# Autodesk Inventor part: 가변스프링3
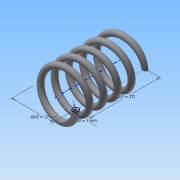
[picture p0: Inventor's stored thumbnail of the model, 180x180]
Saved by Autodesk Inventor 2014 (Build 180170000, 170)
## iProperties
Created: 2015-09
Part Number: 가변스프링3
Material: 강철, 탄소
Document SubType Name: Modeling
Designer: study
Density: 1 g/cm^3
Appearance: 반연마
Mass: 2.40066 g
Surface Area: 32.5308 cm^2
Volume: 2.40066 cm^3
Author: study
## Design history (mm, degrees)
sketch "스케치1"
  geometry: L1 (0, 0)-(11, 0); L2 (11, 0)-(11, 37); L3 (11, 37)-(0, 37); L4 (0, 37)-(0, 0); C1 r 1.5 at (11, 0)
  constraints: 8 end point, 2 parallel, 1 centre point, 1 coincident, 1 horizontal, 1 perpendicular
  dimensions: "d0" = 3 diameter of C1; "d2" = 22 diameter of L2 L4; "d3" = 37 distance of L1.end L2.end (derived)
feature "코일1" sketch "스케치1" pitch "d4" = 10; turns "d6" = 5; dims "d5" = 37 (= d3), "d7" = 0, angle "d8" = 90 deg, angle "d9" = 90 deg, "d10" = 0, "d11" = 0
node "작업 평면1"
sketch "스케치2"
  geometry: L1 (-12.5, 0)-(-9.5, 0) reference; 1 further point
  constraints: 1 horizontal alignment
extrude "돌출1" cut sketch "스케치2" stored distance "d13" = 10; taper "d14" = 0 deg
node "작업 평면2"
sketch "스케치3"
  geometry: L1 (-9.5, 0)-(-12.5, 0) reference; 1 further point
  constraints: 1 horizontal alignment
extrude "돌출2" cut sketch "스케치3" stored distance "d16" = 10; taper "d17" = 0 deg
node "솔리드1"
node "절단 모서리 투영1"
node "절단 모서리 투영2"
other parameters: "d12" = 0, "d15" = 37 (= d3)
